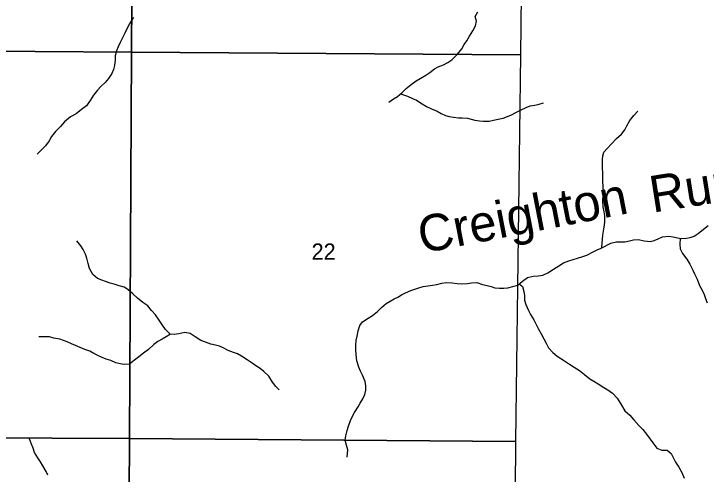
# Model space of a CAD drawing. Extents: x -10 to 158, y 8 to 33.
# Drawn here: x -6.322 to -4.528, y 12.793 to 13.985 of the extents above; entities that cross this region are included whole.
import ezdxf

# ---------------------------------------------------------------- set-up
doc = ezdxf.new("R2010")
doc.units = 0
for name, color, linetype in [('GM_X_Corporation', 7, 'Continuous'), ('GM_X_Minor_River', 7, 'Continuous'), ('GM_X_Minor_River_Text', 7, 'Continuous'), ('GM_X_Section_Text', 7, 'Continuous')]:
    doc.layers.add(name, color=color, linetype=linetype)

msp = doc.modelspace()

# ---------------------------------------------------------------- linework, layer by layer
at = {"layer": 'GM_X_Corporation'}
for points in [[(-7.0152, 14.8959), (-6.0105, 14.8894), (-6.0166, 13.8862), (-7.016, 13.8932)], [(-6.0105, 14.8894), (-4.9975, 14.8842), (-5.0085, 13.879), (-6.0166, 13.8862)], [(-7.016, 13.8932), (-6.0166, 13.8862), (-6.0224, 12.8846), (-7.0267, 12.8896)], [(-5.0085, 13.879), (-5.0215, 12.8769), (-6.0224, 12.8846), (-6.0166, 13.8862)], [(-6.0224, 12.8846), (-6.0285, 11.878), (-7.0382, 11.889), (-7.0267, 12.8896)], [(-6.0224, 12.8846), (-5.0215, 12.8769), (-5.0291, 11.8669), (-6.0285, 11.878)]]:
    msp.add_lwpolyline(points, close=True, dxfattribs=at)
at = {"layer": 'GM_X_Minor_River'}
for points in [[(-6.011, 13.9747), (-6.0146, 13.9725), (-6.022, 13.9591), (-6.0291, 13.9462), (-6.034, 13.9355), (-6.0407, 13.9215), (-6.0459, 13.9112), (-6.0511, 13.8998), (-6.056, 13.8899), (-6.0593, 13.8766), (-6.0592, 13.866), (-6.0607, 13.8519), (-6.0636, 13.8409), (-6.0677, 13.831), (-6.0767, 13.8177), (-6.0849, 13.8078), (-6.0962, 13.7971), (-6.1052, 13.7875), (-6.1154, 13.7746), (-6.1236, 13.7612), (-6.1333, 13.7471), (-6.1461, 13.7372), (-6.1604, 13.7265), (-6.1751, 13.7188), (-6.1906, 13.7058), (-6.2007, 13.6936), (-6.2135, 13.6806), (-6.2244, 13.668), (-6.23, 13.6566), (-6.2393, 13.6437), (-6.2506, 13.6322), (-6.2611, 13.6215)], [(-5.3503, 13.7569), (-5.3376, 13.7654), (-5.3274, 13.7716), (-5.3153, 13.7815), (-5.3048, 13.7922), (-5.2924, 13.8025), (-5.2792, 13.8117), (-5.2691, 13.8182), (-5.254, 13.8267), (-5.2442, 13.8332), (-5.2318, 13.8427), (-5.222, 13.8477), (-5.2087, 13.8531), (-5.1971, 13.8593), (-5.1865, 13.8665), (-5.1722, 13.8807), (-5.161, 13.8948), (-5.1546, 13.9062), (-5.1483, 13.9157), (-5.1411, 13.9275), (-5.1322, 13.9412), (-5.1254, 13.9542), (-5.1225, 13.9663), (-5.126, 13.9781), (-5.1193, 13.991)], [(-5.3197, 13.7779), (-5.3013, 13.7721), (-5.2884, 13.7661), (-5.2785, 13.7613), (-5.2637, 13.7519), (-5.2526, 13.7451), (-5.2394, 13.7391), (-5.2249, 13.7328), (-5.2143, 13.7275), (-5.2033, 13.7223), (-5.1938, 13.7193), (-5.1821, 13.7175), (-5.1696, 13.716), (-5.1597, 13.7157), (-5.1465, 13.7147), (-5.1366, 13.7121), (-5.1271, 13.7099), (-5.115, 13.708), (-5.1048, 13.707), (-5.0904, 13.7074), (-5.0787, 13.7102), (-5.0666, 13.7125), (-5.0541, 13.7153), (-5.0424, 13.7195), (-5.0322, 13.7241), (-5.0213, 13.7295), (-5.0073, 13.7364), (-4.9941, 13.7429), (-4.9843, 13.7468), (-4.9719, 13.7488), (-4.9609, 13.7515), (-4.9492, 13.7546)], [(-4.7978, 13.3797), (-4.7975, 13.391), (-4.7965, 13.4005), (-4.7954, 13.4115), (-4.7936, 13.4222), (-4.7921, 13.4328), (-4.7907, 13.4453), (-4.7908, 13.462), (-4.792, 13.4726), (-4.7944, 13.4855), (-4.7953, 13.5018), (-4.7946, 13.5151), (-4.7948, 13.5394), (-4.7952, 13.5496), (-4.7957, 13.5614), (-4.7958, 13.5746), (-4.7966, 13.5849), (-4.7963, 13.5963), (-4.7968, 13.6076), (-4.7957, 13.6171), (-4.7927, 13.627), (-4.7845, 13.6369), (-4.7728, 13.6487), (-4.7604, 13.6621), (-4.7469, 13.6732), (-4.7383, 13.685), (-4.7338, 13.6953), (-4.7256, 13.709), (-4.7151, 13.7216), (-4.7049, 13.733)], [(-4.5351, 13.4276), (-4.5227, 13.4368)], [(-5.4581, 12.837), (-5.4565, 12.8559), (-5.4596, 12.8676), (-5.4635, 12.8809), (-5.4613, 12.8919), (-5.4579, 12.9056), (-5.455, 12.9166), (-5.4498, 12.9318), (-5.4446, 12.9432), (-5.4394, 12.9527), (-5.4296, 12.9668), (-5.4244, 12.9763), (-5.4177, 12.9878), (-5.4124, 12.9988), (-5.4099, 13.0102), (-5.4096, 13.0212), (-5.4112, 13.0326), (-5.4185, 13.0492), (-5.4235, 13.0598), (-5.4277, 13.0696), (-5.4327, 13.0863), (-5.4351, 13.103), (-5.4352, 13.114), (-5.4357, 13.1272), (-5.4346, 13.1386), (-5.4324, 13.1504), (-5.4295, 13.1641), (-5.425, 13.1781), (-5.4179, 13.1876), (-5.4036, 13.1972), (-5.3923, 13.2034), (-5.3795, 13.2137), (-5.369, 13.2244), (-5.3566, 13.2351), (-5.3468, 13.2408), (-5.3366, 13.2469), (-5.3268, 13.2516), (-5.317, 13.2573), (-5.3068, 13.2627), (-5.2928, 13.2688), (-5.283, 13.2723), (-5.2724, 13.2758), (-5.2615, 13.2789), (-5.249, 13.2809), (-5.2373, 13.2821), (-5.2256, 13.284), (-5.2127, 13.2875), (-5.2018, 13.2891), (-5.1859, 13.2881), (-5.173, 13.2863), (-5.1616, 13.2856), (-5.1461, 13.2868), (-5.1359, 13.2884), (-5.1219, 13.2893), (-5.1071, 13.284), (-5.0957, 13.2814), (-5.0847, 13.2789), (-5.0753, 13.2755), (-5.0631, 13.2748), (-5.0522, 13.2745), (-5.042, 13.2757), (-5.0284, 13.2785), (-5.0159, 13.2827), (-5.0039, 13.2923), (-4.9907, 13.3018), (-4.9759, 13.3053), (-4.9635, 13.3066), (-4.9514, 13.3085), (-4.9382, 13.3143), (-4.9235, 13.3235), (-4.9099, 13.3327), (-4.8971, 13.3403), (-4.8835, 13.345), (-4.8722, 13.3485), (-4.8608, 13.3523), (-4.8472, 13.357), (-4.8374, 13.3601), (-4.8208, 13.3685), (-4.8103, 13.3735), (-4.8001, 13.3785), (-4.7752, 13.3912), (-4.7605, 13.3947), (-4.7495, 13.3944), (-4.7385, 13.3948), (-4.7264, 13.3968), (-4.7162, 13.3999), (-4.703, 13.4007), (-4.6882, 13.397), (-4.6727, 13.3952), (-4.6628, 13.398), (-4.6519, 13.4026), (-4.641, 13.408), (-4.6247, 13.4096), (-4.6137, 13.4074), (-4.602, 13.4052), (-4.5917, 13.4033), (-4.5792, 13.4038), (-4.569, 13.4058), (-4.5588, 13.4089), (-4.5483, 13.4165), (-4.5351, 13.4276)], [(-4.5953, 13.404), (-4.5962, 13.3889), (-4.595, 13.3768), (-4.5888, 13.3647), (-4.5781, 13.3499), (-4.5705, 13.3371), (-4.5624, 13.3216), (-4.5582, 13.3118), (-4.5513, 13.2982), (-4.5447, 13.2819), (-4.5386, 13.2694), (-4.5332, 13.2584), (-4.5297, 13.2475), (-4.5255, 13.2369)], [(-5.6345, 13.0108), (-5.6431, 13.0201), (-5.6518, 13.0314), (-5.6614, 13.0465), (-5.6744, 13.059), (-5.6839, 13.0665), (-5.6945, 13.0733), (-5.704, 13.0804), (-5.717, 13.0887), (-5.7318, 13.0984), (-5.7424, 13.1041), (-5.7527, 13.1078), (-5.7663, 13.113), (-5.7793, 13.1201), (-5.7891, 13.1246), (-5.7994, 13.1268), (-5.8115, 13.1298), (-5.8252, 13.135), (-5.8373, 13.1391), (-5.8517, 13.1481), (-5.865, 13.1575), (-5.8791, 13.1593), (-5.8942, 13.1562), (-5.9063, 13.1542), (-5.9169, 13.1553), (-5.9287, 13.1674), (-5.9363, 13.1783), (-5.9451, 13.1919), (-5.9543, 13.2051), (-5.9654, 13.2168), (-5.9745, 13.2285), (-5.9879, 13.2375), (-6.0012, 13.2488), (-6.0137, 13.2601), (-6.0267, 13.2707), (-6.0362, 13.2774), (-6.0487, 13.2808), (-6.0616, 13.2849), (-6.0718, 13.2871), (-6.0844, 13.2919), (-6.0938, 13.2953), (-6.1049, 13.2998), (-6.1174, 13.3103), (-6.1255, 13.3254), (-6.129, 13.3387), (-6.1328, 13.3523), (-6.1363, 13.3625), (-6.1421, 13.3746), (-6.1478, 13.3844), (-6.1589, 13.3976)], [(-5.0123, 13.2856), (-5.0034, 13.2786), (-4.9999, 13.2657), (-4.9987, 13.2547), (-4.9982, 13.2438), (-4.9955, 13.232), (-4.9886, 13.2165), (-4.9828, 13.2063), (-4.9748, 13.1927), (-4.9682, 13.1802), (-4.9629, 13.17), (-4.9552, 13.156), (-4.9483, 13.1436), (-4.9426, 13.1322), (-4.936, 13.1201), (-4.925, 13.108), (-4.9143, 13.0986), (-4.9048, 13.0926), (-4.8949, 13.0859), (-4.882, 13.0776), (-4.8695, 13.0697), (-4.8561, 13.0615), (-4.8428, 13.0505), (-4.8295, 13.04), (-4.8192, 13.0332), (-4.8075, 13.0269), (-4.7934, 13.0171), (-4.7828, 13.0111), (-4.7702, 13.0024), (-4.7588, 12.9892), (-4.75, 12.976), (-4.7389, 12.9571), (-4.7255, 12.9451), (-4.7156, 12.933), (-4.7022, 12.9183), (-4.6923, 12.9081), (-4.6824, 12.896), (-4.6729, 12.8832), (-4.666, 12.8734), (-4.6553, 12.8602), (-4.6431, 12.855), (-4.6291, 12.855), (-4.6181, 12.846), (-4.6135, 12.8358), (-4.6077, 12.8241), (-4.5989, 12.8105), (-4.5913, 12.7973), (-4.5844, 12.7825)], [(-5.9158, 13.1552), (-5.9267, 13.1488), (-5.9372, 13.1427), (-5.9485, 13.1361), (-5.9587, 13.1285), (-5.973, 13.1159), (-5.9854, 13.1063), (-5.9982, 13.0968), (-6.0088, 13.088), (-6.0223, 13.078), (-6.0359, 13.0764), (-6.0462, 13.0783), (-6.0572, 13.0812), (-6.0708, 13.0868), (-6.0826, 13.0909), (-6.0932, 13.095), (-6.1042, 13.1003), (-6.1145, 13.1055), (-6.1251, 13.1111), (-6.138, 13.116), (-6.1498, 13.1208), (-6.1619, 13.1257), (-6.1725, 13.1305), (-6.1836, 13.1358), (-6.193, 13.1391), (-6.2029, 13.1425), (-6.2184, 13.1454), (-6.2294, 13.1484), (-6.2434, 13.1487), (-6.2571, 13.1482)], [(-6.2341, 12.7896), (-6.2384, 12.7998), (-6.2468, 12.8145), (-6.2529, 12.8243), (-6.2594, 12.8345), (-6.2682, 12.8489), (-6.2713, 12.8603), (-6.2759, 12.8705), (-6.2813, 12.8845)]]:
    msp.add_lwpolyline(points, dxfattribs=at)

# ---------------------------------------------------------------- texts
at = {"layer": 'GM_X_Minor_River_Text'}
for s, rotation, p in [('Run', 9.0005, (-4.6666, 13.47)), ('Creighton', 10.9986, (-5.2645, 13.3643))]:
    msp.add_text(s, height=0.09469, rotation=rotation, dxfattribs=at).set_placement(p)
at = {"layer": 'GM_X_Section_Text'}
msp.add_text('22', height=0.04186, rotation=0, dxfattribs=at).set_placement((-5.5502, 13.3485))

doc.saveas('drawing.dxf')
